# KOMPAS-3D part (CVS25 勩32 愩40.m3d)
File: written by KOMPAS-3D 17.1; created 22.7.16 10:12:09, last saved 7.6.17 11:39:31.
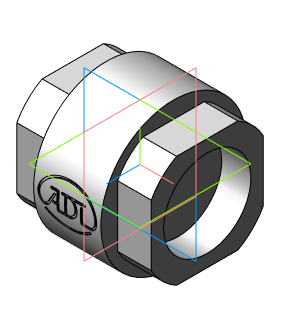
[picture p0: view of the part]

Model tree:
1. Операция без истории:2  (labels: Сталь 20  ГОСТ 1050-88)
